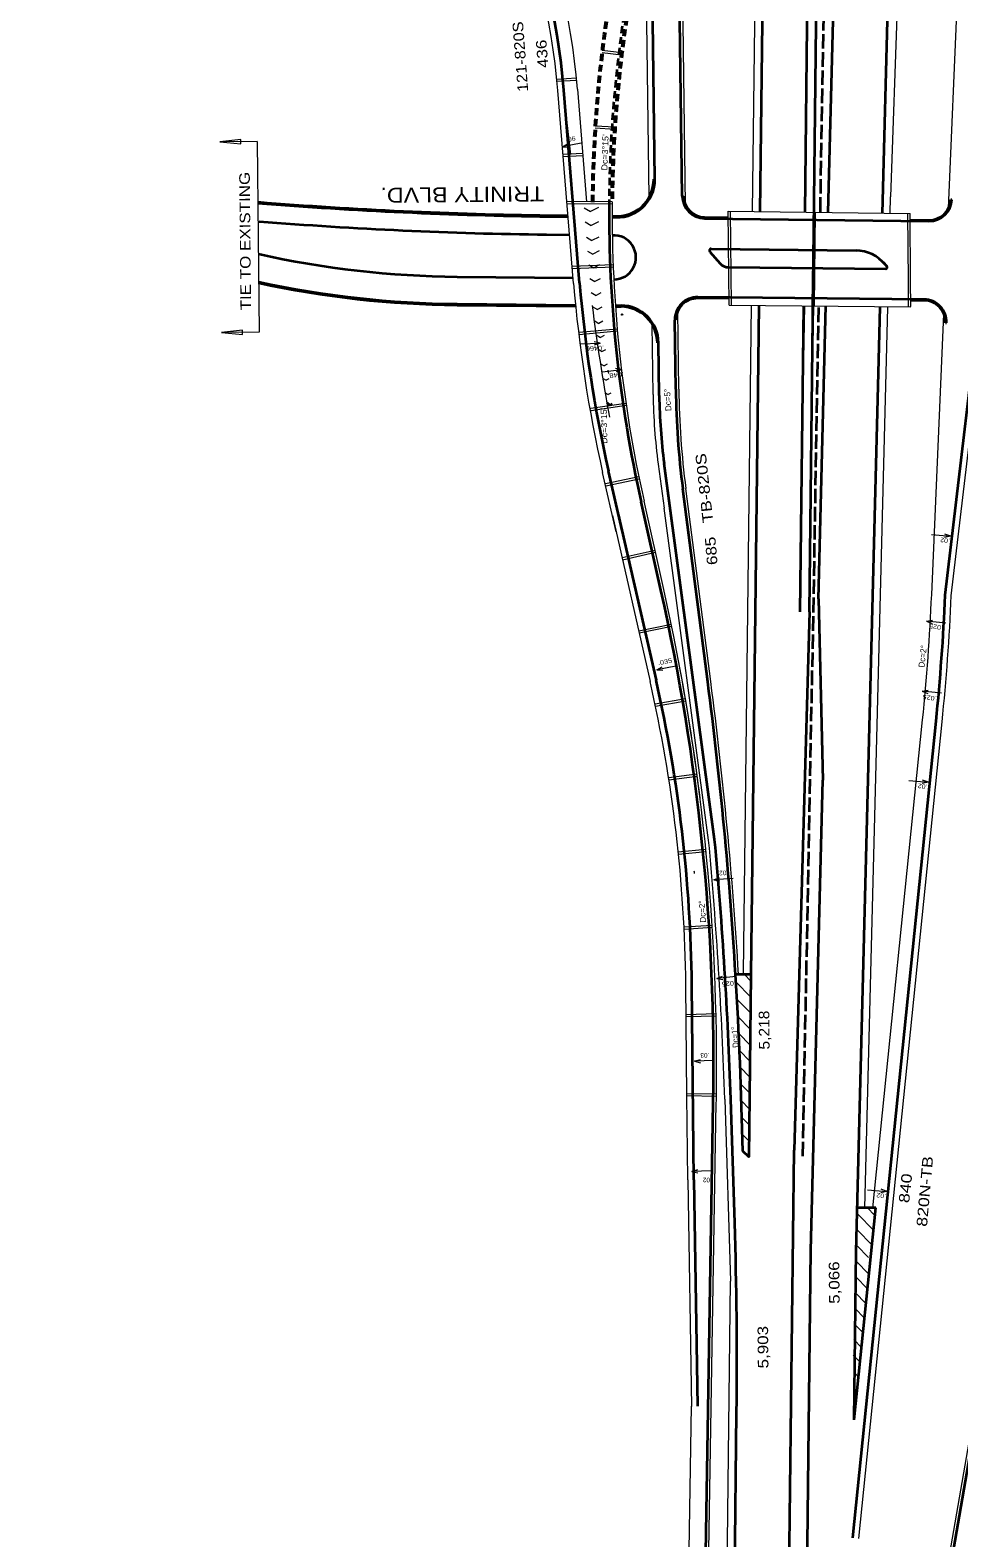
# Model space of a CAD drawing. Extents: x 2354993 to 2372084, y 6966390 to 6990057.
# Drawn here: x 2363436 to 2364667, y 6974745 to 6976742 of the extents above; entities that cross this region are included whole.
import ezdxf

# ---------------------------------------------------------------- set-up
doc = ezdxf.new("R2010")
doc.units = 0
doc.header["$LTSCALE"] = 3.2
doc.header["$PDMODE"] = 32
doc.header["$PDSIZE"] = 1.6
doc.linetypes.add('LONG_DASHED', pattern=[7.5, 6, -1.5])
doc.linetypes.add('MEDIUM_DASHED', pattern=[4.5, 3, -1.5])
for name, color, linetype, lineweight in [('12', 7, 'Continuous', 13), ('13', 7, 'Continuous', 13), ('15', 7, 'Continuous', 13), ('17', 7, 'Continuous', 13), ('19', 7, 'Continuous', 13), ('2', 7, 'Continuous', 35), ('4', 7, 'Continuous', 13), ('5', 7, 'Continuous', 35), ('59', 7, 'Continuous', 25), ('61', 7, 'Continuous', 13), ('9', 7, 'Continuous', 13)]:
    doc.layers.add(name, color=color, linetype=linetype, lineweight=lineweight)

msp = doc.modelspace()

# ---------------------------------------------------------------- linework, layer by layer
at = {"layer": '12'}
for p, q in [((2364220.257, 6976711.848), (2364194.449, 6976714.999)), ((2364219.897, 6976708.869), (2364194.088, 6976712.022)), ((2364133.973, 6976677.267), (2364159.889, 6976678.781)), ((2364134.463, 6976674.273), (2364160.421, 6976675.79)), ((2364211.052, 6976613.311), (2364185.106, 6976614.994)), ((2364210.86, 6976610.318), (2364184.914, 6976612.001)), ((2364142.53, 6976577.625), (2364168.486, 6976579.108)), ((2364142.702, 6976574.452), (2364168.659, 6976575.935)), ((2364207.447, 6976514.419), (2364147.557, 6976514.903)), ((2364207.426, 6976511.42), (2364147.802, 6976511.901)), ((2364365.503, 6976377.938), (2364364.413, 6976502.287)), ((2364473.677, 6976500.882), (2364472.212, 6976376.913)), ((2364476.676, 6976500.845), (2364475.212, 6976376.884)), ((2364600.009, 6976409.93), (2364599.244, 6976499.34)), ((2364208.761, 6976431.2), (2364154.576, 6976428.959)), ((2364208.882, 6976428.202), (2364154.82, 6976425.966)), ((2364600.298, 6976375.862), (2364600.009, 6976409.929)), ((2364214.213, 6976346.179), (2364163.688, 6976341.61)), ((2364214.481, 6976343.191), (2364163.957, 6976338.622)), ((2364225.766, 6976247.764), (2364179.442, 6976240.906)), ((2364226.203, 6976244.796), (2364179.88, 6976237.938)), ((2364242.847, 6976150.358), (2364198.654, 6976141.231)), ((2364243.451, 6976147.42), (2364199.26, 6976138.293)), ((2364264.361, 6976053.073), (2364220.592, 6976043.251)), ((2364265.018, 6976050.146), (2364221.248, 6976040.323)), ((2364285.945, 6975955.107), (2364242.71, 6975946.195)), ((2364286.552, 6975952.169), (2364243.315, 6975943.257)), ((2364304.638, 6975856.27), (2364264.508, 6975849.448)), ((2364305.14, 6975853.312), (2364265.011, 6975846.49)), ((2364319.874, 6975756.807), (2364282.37, 6975751.77)), ((2364320.273, 6975753.834), (2364282.768, 6975748.797)), ((2364331.63, 6975656.874), (2364295.111, 6975653.262)), ((2364331.924, 6975653.887), (2364295.406, 6975650.275)), ((2364339.896, 6975556.492), (2364302.698, 6975554.122)), ((2364340.087, 6975553.498), (2364302.889, 6975551.127)), ((2364345.101, 6975439.16), (2364305.463, 6975438.251)), ((2364345.169, 6975436.16), (2364305.532, 6975435.251)), ((2364345.646, 6975329.954), (2364306.637, 6975330.608)), ((2364345.687, 6975332.954), (2364306.687, 6975333.608))]:
    msp.add_line(p, q, dxfattribs=at)
at = {"layer": '12', "lineweight": 35}
for radius, start in [(48.5, 262.08834), (50, 262.33221)]:
    msp.add_arc((2364214.072, 6976544.083), radius, start, 0.75286, dxfattribs=at)
at = {"layer": '15'}
for p, q in [((2363737.301, 6976594.496), (2363687.464, 6976594.035)), ((2363737.301, 6976594.496), (2363739.638, 6976342.006)), ((2363739.638, 6976342.006), (2363689.801, 6976341.545))]:
    msp.add_line(p, q, dxfattribs=at)
for points in [[(2363687.464, 6976594.035), (2363715.49, 6976591.295), (2363715.435, 6976597.294)], [(2363689.801, 6976341.545), (2363717.827, 6976338.805), (2363717.772, 6976344.804)]]:
    msp.add_lwpolyline(points, close=True, dxfattribs=at)
at = {"layer": '17'}
for p, q in [((2364141.227, 6976587.593), (2364148.646, 6976591.34)), ((2364191.5, 6976327.281), (2364183.578, 6976324.764))]:
    msp.add_line(p, q, dxfattribs=at)
for points in [[(2364166.545, 6976592.466), (2364141.227, 6976587.593), (2364149.501, 6976586.869)], [(2364165.729, 6976326.505), (2364191.5, 6976327.281), (2364183.447, 6976329.314)]]:
    msp.add_lwpolyline(points, dxfattribs=at)
at = {"layer": '19'}
for p, q in [((2364201.86, 6976291.634), (2364202.424, 6976287.331)), ((2364220.228, 6976292.798), (2364212.603, 6976289.49)), ((2364656.189, 6976071.819), (2364648.034, 6976070.216)), ((2364623.803, 6975959.304), (2364631.519, 6975956.212)), ((2364266.473, 6975895.028), (2364273.894, 6975898.772)), ((2364618.261, 6975866.445), (2364625.977, 6975863.353)), ((2364626.461, 6975746.048), (2364618.306, 6975744.445)), ((2364342.025, 6975617.021), (2364349.845, 6975619.84)), ((2364346.086, 6975486.183), (2364353.826, 6975489.214)), ((2364316.438, 6975376.461), (2364324.327, 6975379.082)), ((2364313.124, 6975230.56), (2364321.013, 6975233.181)), ((2364571.644, 6975204.112), (2364563.489, 6975202.509))]:
    msp.add_line(p, q, dxfattribs=at)
for points in [[(2364194.67, 6976289.408), (2364220.228, 6976292.798), (2364212.01, 6976294.003)], [(2364630.496, 6976073.972), (2364656.189, 6976071.819), (2364648.419, 6976074.753)], [(2364649.449, 6975956.645), (2364623.803, 6975959.304), (2364631.982, 6975960.742)], [(2364291.794, 6975899.89), (2364266.473, 6975895.028), (2364274.748, 6975894.299)], [(2364643.907, 6975863.786), (2364618.261, 6975866.445), (2364626.44, 6975867.883)], [(2364600.768, 6975748.201), (2364626.461, 6975746.048), (2364618.691, 6975748.982)], [(2364367.749, 6975618.785), (2364342.025, 6975617.021), (2364350.151, 6975615.297)], [(2364371.752, 6975488.648), (2364346.086, 6975486.183), (2364354.256, 6975484.681)], [(2364342.199, 6975377.575), (2364316.438, 6975376.461), (2364324.518, 6975374.532)], [(2364338.885, 6975231.674), (2364313.124, 6975230.56), (2364321.204, 6975228.631)], [(2364545.951, 6975206.265), (2364571.644, 6975204.112), (2364563.874, 6975207.046)]]:
    msp.add_lwpolyline(points, dxfattribs=at)
at = {"layer": '2'}
for p, q in [((2364530.922, 6975124.614), (2364562.664, 6976375.097)), ((2364291.753, 6976266.396), (2364290.548, 6976357.962)), ((2364334.203, 6975878.802), (2364301.128, 6976134.434)), ((2364470.941, 6975126.137), (2364486.746, 6975748.807)), ((2364556.956, 6975182.505), (2364533.106, 6975182.46))]:
    msp.add_line(p, q, dxfattribs=at)
for centre, radius, start, end in [((2364320.545, 6976358.356), 30, 89.45039, 180.7541), ((2364320.545, 6976358.356), 28.5, 89.45039, 180.7541), ((2365437.57, 6976281.475), 1145.916, 180.75397, 187.37241), ((2358651.991, 6975143.593), 5729.578, 3.48146, 7.37242)]:
    msp.add_arc(centre, radius, start, end, dxfattribs=at)
at = {"layer": '4'}
for centre, radius, start, end in [((2367023.768, 6976739.288), 2865.742, 187.25475, 190.24927), ((2365933.209, 6976336.345), 1644.505, 183.76571, 187.20199), ((2359028.554, 6975149.626), 5309.334, 5.14125, 5.17258), ((2358640.15, 6975142.702), 5741.452, 3.90795, 4.84638)]:
    msp.add_arc(centre, radius, start, end, dxfattribs=at)
at = {"layer": '5', "linetype": 'LONG_DASHED'}
for p, q in [((2364483.383, 6976501.515), (2364499.337, 6977426.187)), ((2364474.238, 6975971.435), (2364481.232, 6976376.826)), ((2364460.157, 6975250.802), (2364474.238, 6975971.435))]:
    msp.add_line(p, q, dxfattribs=at)
at = {"layer": '5'}
for p, q in [((2364463.051, 6976501.012), (2364473.085, 6977351.601)), ((2364468.806, 6975971.515), (2364485.084, 6977351.459)), ((2364410.695, 6977127.236), (2364403.178, 6976501.747)), ((2364264.089, 6976544.74), (2364257.91, 6977015.279)), ((2364493.827, 6976500.634), (2364506.22, 6976988.835)), ((2364300.388, 6976522.254), (2364296.153, 6976843.963)), ((2364565.808, 6976498.964), (2364574.043, 6976823.383)), ((2364164.368, 6976407.34), (2364143.529, 6976662.499)), ((2364262.568, 6976544.72), (2364264.067, 6976544.74)), ((2364300.388, 6976522.254), (2364301.888, 6976522.273)), ((2364656.126, 6976517.745), (2364657.625, 6976517.68)), ((2364123.617, 6976495.195), (2364149.192, 6976494.879)), ((2364123.635, 6976496.695), (2364149.069, 6976496.381)), ((2364330.033, 6976494.151), (2364361.488, 6976493.763)), ((2364330.015, 6976492.651), (2364627.284, 6976488.986)), ((2364602.317, 6976490.794), (2364627.302, 6976490.486)), ((2364120.669, 6976471.23), (2364151.154, 6976470.854)), ((2364336.964, 6976448.401), (2364350.554, 6976433.023)), ((2364338.869, 6976452.556), (2364530.747, 6976450.191)), ((2364566.457, 6976434.552), (2364571.393, 6976429.333)), ((2364002.302, 6976415.429), (2364155.802, 6976413.952)), ((2364361.651, 6976427.956), (2364569.921, 6976425.959)), ((2364001.941, 6976377.929), (2364159.127, 6976376.416)), ((2364001.955, 6976379.429), (2364158.979, 6976377.918)), ((2364211.726, 6976377.411), (2364219.404, 6976377.336)), ((2364211.832, 6976375.91), (2364219.389, 6976375.836)), ((2364362.428, 6976386.456), (2364320.819, 6976386.855)), ((2364620.831, 6976385.478), (2364320.833, 6976388.355)), ((2364401.688, 6976377.59), (2364391.039, 6975491.379)), ((2364456.807, 6975971.657), (2364461.589, 6976377.014)), ((2364480.837, 6975988.89), (2364490.682, 6976376.735)), ((2364620.817, 6976383.978), (2364603.227, 6976384.147)), ((2364292.048, 6976357.981), (2364290.548, 6976357.962)), ((2364649.017, 6976354.241), (2364650.515, 6976354.176)), ((2364267.418, 6976327.975), (2364268.918, 6976327.994)), ((2364269.836, 6976258.002), (2364268.918, 6976327.994)), ((2364648.854, 6975993.703), (2364685.177, 6976299.01)), ((2364200.335, 6976248.675), (2364204.407, 6976245.459)), ((2364207.677, 6976247.074), (2364204.407, 6976245.459)), ((2364220.612, 6976079.202), (2364202.682, 6976158.073)), ((2364343.25, 6975670.276), (2364276.437, 6976168.108)), ((2364272.091, 6976000.348), (2364245.819, 6976117.442)), ((2364215.66, 6976100.99), (2364265.672, 6975880.999)), ((2364592.006, 6974338.873), (2364898.046, 6976104.929)), ((2364480.837, 6975988.89), (2364486.746, 6975748.807)), ((2364468.806, 6975971.515), (2364448.514, 6975258.741)), ((2364526.462, 6974745.451), (2364636.721, 6975826.723)), ((2364315.808, 6975219.612), (2364313.082, 6975477.787)), ((2364391.039, 6975491.379), (2364370.876, 6975491.58)), ((2364320, 6974037.948), (2364341.522, 6975321.854)), ((2364369.882, 6975162.803), (2364364.645, 6975326.411)), ((2364405.885, 6971647.215), (2364448.514, 6975258.72)), ((2364315.808, 6975219.612), (2364320.778, 6974919.647)), ((2364528.304, 6974901.522), (2364556.956, 6975182.505)), ((2364429.884, 6971646.932), (2364470.958, 6975126.824)), ((2364528.304, 6974901.519), (2364530.952, 6975125.889)), ((2364365.094, 6974291.579), (2364372.415, 6974911.86))]:
    msp.add_line(p, q, dxfattribs=at)
at = {"layer": '5', "lineweight": 13}
for p, q in [((2364401.898, 6977227.474), (2364393.18, 6976501.87)), ((2364256.409, 6976520.423), (2364250.238, 6976989.323)), ((2364592.679, 6976978.427), (2364576.375, 6976521.182)), ((2364304.541, 6976510.635), (2364300.153, 6976844.016)), ((2364653.122, 6976506.192), (2364666.284, 6976808.9)), ((2364156.395, 6976406.689), (2364135.555, 6976661.848)), ((2364161.469, 6976663.965), (2364173.652, 6976514.8)), ((2364575.805, 6976498.71), (2364576.378, 6976521.284)), ((2364170.291, 6976506.807), (2364178.765, 6976501.813)), ((2364189.404, 6976507.068), (2364178.765, 6976501.813)), ((2364362.502, 6976377.967), (2364361.414, 6976502.26)), ((2364361.414, 6976502.26), (2364602.244, 6976499.303)), ((2364370.176, 6976502.124), (2364370.176, 6976502.154)), ((2364603.008, 6976409.955), (2364602.244, 6976499.303)), ((2364171.823, 6976488.054), (2364179.575, 6976483.485)), ((2364189.432, 6976488.353), (2364179.575, 6976483.485)), ((2364173.477, 6976467.794), (2364180.633, 6976463.577)), ((2364189.687, 6976468.048), (2364180.633, 6976463.577)), ((2364174.971, 6976449.502), (2364181.753, 6976445.505)), ((2364190.12, 6976449.638), (2364181.753, 6976445.505)), ((2364006.399, 6976415.384), (2364032.152, 6976415.14)), ((2364176.465, 6976431.212), (2364183.032, 6976427.341)), ((2364190.748, 6976431.153), (2364183.032, 6976427.341)), ((2364177.959, 6976412.919), (2364184.474, 6976409.079)), ((2364179.511, 6976394.592), (2364186.08, 6976390.719)), ((2364191.576, 6976412.587), (2364184.474, 6976409.079)), ((2364192.604, 6976393.942), (2364186.08, 6976390.719)), ((2364603.297, 6976375.834), (2364603.008, 6976409.954)), ((2364181.117, 6976376.233), (2364187.856, 6976372.262)), ((2364193.836, 6976375.216), (2364187.856, 6976372.262)), ((2364362.722, 6976377.965), (2364603.299, 6976375.652)), ((2364391.688, 6976377.687), (2364381.059, 6975493.135)), ((2364542.394, 6975182.478), (2364572.661, 6976374.843)), ((2364183.59, 6976357.364), (2364189.801, 6976353.703)), ((2364195.276, 6976356.408), (2364189.801, 6976353.703)), ((2364295.753, 6976266.449), (2364294.394, 6976369.687)), ((2364630.871, 6975994.486), (2364647.026, 6976366.008)), ((2364186.203, 6976338.413), (2364191.923, 6976335.042)), ((2364196.925, 6976337.513), (2364191.923, 6976335.042)), ((2364261.819, 6976259.529), (2364260.601, 6976352.14)), ((2364188.957, 6976319.377), (2364194.221, 6976316.274)), ((2364198.79, 6976318.531), (2364194.221, 6976316.274)), ((2364191.856, 6976300.257), (2364196.702, 6976297.4)), ((2364200.872, 6976299.46), (2364196.702, 6976297.4)), ((2364656.798, 6975992.758), (2364693.121, 6976298.065)), ((2364194.9, 6976281.051), (2364199.368, 6976278.417)), ((2364203.176, 6976280.298), (2364199.368, 6976278.417)), ((2364198.093, 6976261.757), (2364202.224, 6976259.323)), ((2364205.706, 6976261.043), (2364202.224, 6976259.323)), ((2364212.811, 6976077.429), (2364194.881, 6976156.299)), ((2364268.508, 6976167.044), (2364276.309, 6976108.919)), ((2364338.17, 6975879.315), (2364305.095, 6976134.947)), ((2364275.994, 6976001.224), (2364249.722, 6976118.318)), ((2364207.86, 6976099.217), (2364257.87, 6975879.23)), ((2364335.322, 6975669.213), (2364276.309, 6976108.919)), ((2364588.065, 6974339.557), (2364894.105, 6976105.613)), ((2364534.421, 6974744.639), (2364644.68, 6975825.911)), ((2364552.936, 6975182.498), (2364618.814, 6975828.55)), ((2364306.637, 6975330.608), (2364305.083, 6975477.703)), ((2364390.905, 6975461.658), (2364371.604, 6975481.353)), ((2364391.155, 6975482.834), (2364382.699, 6975491.462)), ((2364390.655, 6975440.483), (2364372.902, 6975458.597)), ((2364390.455, 6975419.26), (2364374.105, 6975435.939)), ((2364390.243, 6975398.048), (2364375.212, 6975413.381)), ((2364390.031, 6975376.836), (2364376.227, 6975390.918)), ((2364389.655, 6975355.791), (2364377.15, 6975368.549)), ((2364389.406, 6975334.618), (2364377.982, 6975346.272)), ((2364307.81, 6975219.527), (2364306.637, 6975330.608)), ((2364324, 6974037.881), (2364345.522, 6975321.787)), ((2364356.648, 6975326.194), (2364364.464, 6975085.406)), ((2364389.156, 6975313.445), (2364378.725, 6975324.087)), ((2364388.906, 6975292.27), (2364379.435, 6975301.932)), ((2364388.656, 6975271.098), (2364380.144, 6975279.781)), ((2364307.81, 6975219.479), (2364312.78, 6974919.515)), ((2364555.717, 6975172.27), (2364545.376, 6975182.836)), ((2364553.737, 6975152.851), (2364533.009, 6975174.027)), ((2364551.757, 6975133.431), (2364532.789, 6975152.809)), ((2364547.225, 6975116.618), (2364531.522, 6975132.66)), ((2364547.796, 6975094.591), (2364530.861, 6975111.891)), ((2364355.095, 6974291.679), (2364364.464, 6975085.406)), ((2364545.816, 6975075.173), (2364530.2, 6975091.124)), ((2364543.836, 6975055.752), (2364529.539, 6975070.356)), ((2364541.856, 6975036.332), (2364528.879, 6975049.589)), ((2364539.875, 6975016.91), (2364528.218, 6975028.821)), ((2364537.895, 6974997.492), (2364527.557, 6975008.053)), ((2364535.915, 6974978.072), (2364526.896, 6974987.286)), ((2364533.935, 6974958.652), (2364529.037, 6974963.653)), ((2364532.131, 6974939.049), (2364528.787, 6974942.466)), ((2364298.003, 6974038.317), (2364312.777, 6974919.68)), ((2364530.151, 6974919.631), (2364528.537, 6974921.279))]:
    msp.add_line(p, q, dxfattribs=at)
at = {"layer": '5'}
msp.add_lwpolyline([(2364391.039, 6975491.379), (2364388.406, 6975249.925), (2364380.853, 6975257.63)], dxfattribs=at)
at = {"layer": '5', "lineweight": 13}
for centre, radius, start, end in [((2363030.028, 6976428.641), 1917.859, 350.16881, 38.12295), ((2363030.028, 6976428.641), 1891.859, 350.16881, 38.12295), ((2363278.934, 6976591.886), 885.473, 4.66908, 79.45368), ((2363278.934, 6976591.886), 859.473, 4.66908, 79.45368), ((2365952.338, 6976500.332), 1744.947, 179.53746, 192.64601), ((2365935.418, 6976551.985), 1784.947, 184.66908, 192.80768), ((2365019.772, 6976267.872), 758, 180.63068, 187.64408), ((2365437.57, 6976281.475), 1141.916, 180.75397, 187.37241), ((2361463.137, 6975370.103), 2882.789, 359.202, 12.64601), ((2361772.783, 6976118.765), 2860.789, 354.17756, 357.51015), ((2361772.783, 6976118.765), 2886.789, 354.17756, 357.51015), ((2361463.137, 6975370.103), 2882.789, 7.0723, 10.53623), ((2362403.348, 6975457.635), 1901.84, 0.60459, 12.80743), ((2358651.991, 6975143.593), 5733.578, 3.48146, 7.37242), ((2358651.99, 6975143.593), 5707.578, 1.83339, 5.28724), ((2361463.137, 6975370.103), 2882.789, 359.03966, 359.202)]:
    msp.add_arc(centre, radius, start, end, dxfattribs=at)
at = {"layer": '5'}
for centre, radius, start, end in [((2363030.028, 6976428.641), 1895.859, 350.16881, 38.12295), ((2363278.934, 6976591.886), 867.473, 4.66908, 79.45368), ((2364194.239, 6982224.338), 5728.078, 265.43333, 269.2949), ((2365952.338, 6976500.332), 1748.947, 179.53746, 192.64601), ((2364330.385, 6976522.648), 30, 180.75408, 269.29367), ((2364330.385, 6976522.648), 28.5, 180.75408, 269.29367), ((2364627.653, 6976518.983), 30, 269.29355, 357.51013), ((2364627.653, 6976518.983), 28.5, 269.29355, 357.51013), ((2364194.239, 6982224.338), 5729.578, 265.43333, 269.2949), ((2364194.239, 6982224.338), 5753.578, 265.46771, 269.26735), ((2364209.911, 6976441.128), 29.142, 269.44369, 94.4484), ((2364014.558, 6977688.61), 1273.24, 257.48616, 269.44843), ((2364338.837, 6976450.057), 2.5, 89.29242, 221.46875), ((2364530.131, 6976400.195), 50, 38.72208, 89.2941), ((2364361.794, 6976442.955), 15, 221.4662, 269.45025), ((2364569.94, 6976427.959), 2, 269.45043, 43.40301), ((2364014.558, 6977688.61), 1310.74, 257.85089, 269.44843), ((2364014.558, 6977688.61), 1309.24, 257.85089, 269.44843), ((2365935.418, 6976551.985), 1776.947, 184.66908, 192.80768), ((2364218.922, 6976327.338), 48.5, 0.75204, 89.44837), ((2364218.922, 6976327.338), 50, 0.75204, 89.44837), ((2364620.544, 6976355.479), 28.5, 357.51013, 89.45048), ((2364620.544, 6976355.479), 30, 357.51013, 89.45048), ((2365019.772, 6976267.872), 750, 180.75406, 187.64408), ((2361463.137, 6975370.103), 2878.789, 359.03966, 12.64601), ((2361772.783, 6976118.765), 2878.789, 354.17756, 357.51015), ((2362403.348, 6975457.635), 1909.84, 0.60459, 12.80745), ((2358651.99, 6975143.593), 5715.578, 1.83339, 5.28724), ((2358651.99, 6975143.593), 5729.578, 1.14036, 3.482), ((2358642.814, 6974979.492), 5730, 359.32371, 1.83328)]:
    msp.add_arc(centre, radius, start, end, dxfattribs=at)
at = {"layer": '5', "linetype": 'MEDIUM_DASHED', "lineweight": 53}
for centre, radius, start, end in [((2365952.337, 6976500.333), 1770.947, 142.90202, 179.54796), ((2365952.338, 6976500.332), 1744.947, 143.1512, 179.53746)]:
    msp.add_arc(centre, radius, start, end, dxfattribs=at)
at = {"layer": '5', "linetype": 'MEDIUM_DASHED'}
msp.add_arc((2365952.338, 6976500.332), 1748.947, 143.1115, 179.53746, dxfattribs=at)
at = {"layer": '59'}
for p, q in [((2364460.597, 6976282.477), (2364462.225, 6976377.008)), ((2364472.412, 6976271.594), (2364474.225, 6976376.942))]:
    msp.add_line(p, q, dxfattribs=at)
at = {"layer": '61'}
msp.add_line((2364140.834, 6976676.787), (2364152.3, 6976577.301), dxfattribs=at)
at = {"layer": '9'}
msp.add_point((2364220.647, 6976365.312), dxfattribs=at)

# ---------------------------------------------------------------- texts
at = {"layer": '12'}
for s, rotation, width, p in [("Dc=3°15'", 87.985, 1.1, (2364201.105, 6976556.063)), ('Dc=1°', 93.639, 0.95, (2364375.156, 6975394.606))]:
    msp.add_text(s, height=8, rotation=rotation, dxfattribs=dict(at, width=width)).set_placement(p)
for s, p in [('Dc=5°', (2364286.07, 6976237.775)), ('Dc=2°', (2364331.92, 6975560.343))]:
    msp.add_text(s, height=8, rotation=93.639, dxfattribs=at).set_placement(p)
at = {"layer": '13'}
for s, rotation, width, p in [('121-820S', 94.338, 1.15, (2364096.276, 6976660.824)), ('436', 94.471, 1.2, (2364123.117, 6976692.438)), ('TB-820S', 96.202, 1.25, (2364341.535, 6976090.401)), ('685', 94.755, 1.2, (2364347.239, 6976034.247)), ('5,218', 90.548, 1.1, (2364416.129, 6975392.092)), ('820N-TB', 84.917, 1.25, (2364624.577, 6975156.965)), ('840', 83.832, 1.25, (2364600.951, 6975188.289)), ('5,066', 90.548, 1.2, (2364508.953, 6975055.436)), ('5,903', 90.548, 1.2, (2364414.579, 6974969.874))]:
    msp.add_text(s, height=14, rotation=rotation, dxfattribs=dict(at, width=width)).set_placement(p)
at = {"layer": '15'}
for s, height, rotation, width, p in [('TIE TO EXISTING', 14, 90.548, 1.2, (2363729.049, 6976370.944)), ('TRINITY BLVD.', 20, 180.548, 1.15, (2364117.385, 6976535.223))]:
    msp.add_text(s, height=height, rotation=rotation, dxfattribs=dict(at, width=width)).set_placement(p)
at = {"layer": '17'}
for s, height, rotation, width, p in [('.06', 6, 10.964, 1.15, (2364146.786, 6976593.577)), ('.0466', 6, 182.937, 1.2, (2364196.621, 6976324.233)), ("Dc=3°15'", 8, 91.084, 1.1, (2364201.219, 6976194.333))]:
    msp.add_text(s, height=height, rotation=rotation, dxfattribs=dict(at, width=width)).set_placement(p)
msp.add_text('Dc=2°', height=8, rotation=83.132, dxfattribs=at).set_placement((2364621.114, 6975897.556))
at = {"layer": '19'}
for s, height, rotation, width, p in [('.048', 6, 187.791, 1.25, (2364222.813, 6976289.649)), ('.02', 6, 171.703, 1.15, (2364655.413, 6976068.334)), ('.025', 6, 171.703, 1.2, (2364646.432, 6975953.335)), ('.035', 5.999, 10.665, 1.25, (2364268.516, 6975900.932)), ('.025', 6, 171.703, 1.2, (2364637.855, 6975859.523)), ('.02', 6, 171.703, 1.15, (2364625.685, 6975742.563)), ('.02', 6, 182.2, 1.1, (2364361.204, 6975629.132)), ('.025', 5.999, 184.969, 1.2, (2364371.173, 6975483.215)), ('.03', 6, 181.281, 1.05, (2364336.153, 6975387.526)), ('.02', 6, 179.223, 1.05, (2364339.456, 6975222.239)), ('.02', 6, 171.703, 1.15, (2364570.868, 6975200.627))]:
    msp.add_text(s, height=height, rotation=rotation, dxfattribs=dict(at, width=width)).set_placement(p)

doc.saveas('drawing.dxf')
